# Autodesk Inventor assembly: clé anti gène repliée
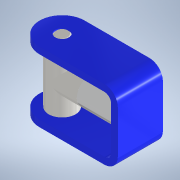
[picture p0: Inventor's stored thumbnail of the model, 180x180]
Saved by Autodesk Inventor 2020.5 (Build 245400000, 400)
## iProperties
Created: 2022-10
Part Number: clé anti gène repliée
Document SubType Name: Assembly
Designer: mel
Author: mel
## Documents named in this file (4)
- D:\travail\année 2022-2023\I2D\procédés\clé anti gène repliée.iam
- D:\travail\année 2022-2023\I2D\procédés\pivot.ipt
- D:\travail\année 2022-2023\I2D\procédés\axe.ipt
- D:\travail\année 2022-2023\I2D\procédés\coque.ipt
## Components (3 placed, 3 different names)
1. pivot:1 — Logement:2, Logement:3
2. axe:1 — Logement:2, Angle:1
3. coque:1 — Logement:3, Angle:1
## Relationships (3: Insert 2, Angle 1)
- Logement:2 [Insert]: pivot:1 ↔ axe:1
- Logement:3 [Insert]: pivot:1 ↔ coque:1
- Angle:1: axe:1 ↔ coque:1
